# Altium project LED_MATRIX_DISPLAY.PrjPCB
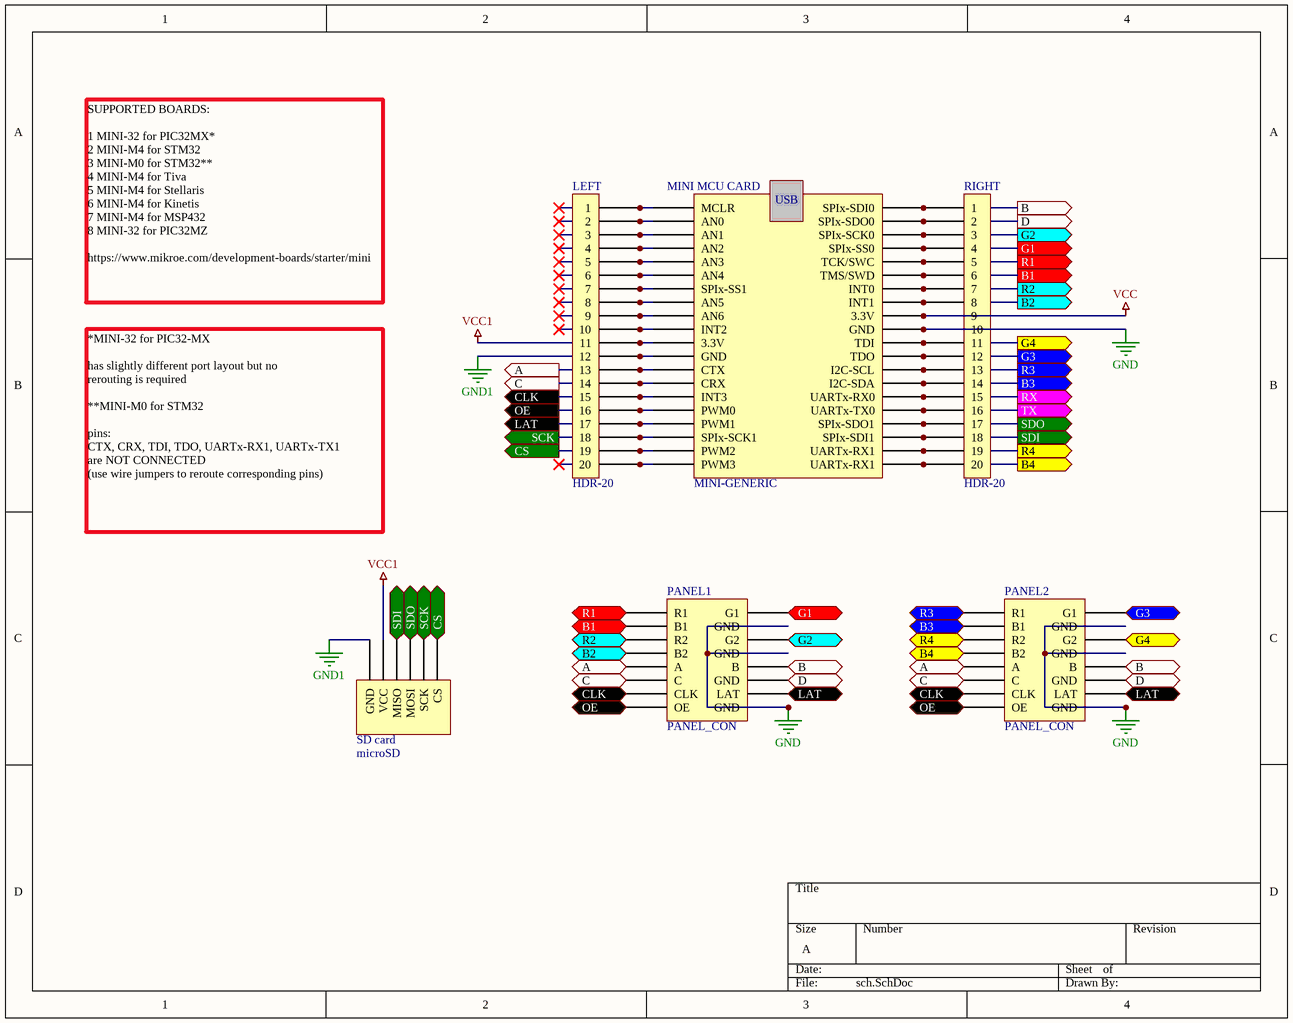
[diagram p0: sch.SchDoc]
1 sheet, 6 parts. Net scope: flat (ports and power ports of the same name join across sheets).
Board file: pcb.PcbDoc

## Sheet sch.SchDoc
size A

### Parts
LEFT  HDR-20  [HDR-20]
MINI_MCU_CARD  MINI-GENERIC  [MINI - GENERIC]
PANEL1  PANEL_CON  [HDR-8x2]
PANEL2  PANEL_CON  [HDR-8x2]
RIGHT  HDR-20  [HDR-20]
SD_card  microSD  [microSD]

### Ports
A (out), B1 (out), B2 (out), B3 (out), B4 (out), B (out), C (out), CLK (out), CS (out), D (out), G1 (out), G2 (out), G3 (out), G4 (out), LAT (out), OE (out), R1 (out), R2 (out), R3 (out), R4 (out), RX (out), SCK (out), SDI (out), SDO (out), TX (out)

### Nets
GND: MINI_MCU_CARD.31(GND) PANEL1.9(GND) PANEL1.13(GND) PANEL1.15(GND) PANEL2.9(GND) PANEL2.13(GND) PANEL2.15(GND) RIGHT.10
GND1: LEFT.12 MINI_MCU_CARD.12(GND) SD_card.1(GND)
VCC: MINI_MCU_CARD.32(3.3V) RIGHT.9
VCC1: LEFT.11 MINI_MCU_CARD.11(3.3V) SD_card.2(VCC)
NetLEFT_1: LEFT.1 MINI_MCU_CARD.1(MCLR)
NetLEFT_2: LEFT.2 MINI_MCU_CARD.2(AN0)
NetLEFT_3: LEFT.3 MINI_MCU_CARD.3(AN1)
NetLEFT_4: LEFT.4 MINI_MCU_CARD.4(AN2)
NetLEFT_5: LEFT.5 MINI_MCU_CARD.5(AN3)
NetLEFT_6: LEFT.6 MINI_MCU_CARD.6(AN4)
NetLEFT_7: LEFT.7 MINI_MCU_CARD.7(SPIx-SS1)
NetLEFT_8: LEFT.8 MINI_MCU_CARD.8(AN5)
NetLEFT_9: LEFT.9 MINI_MCU_CARD.9(AN6)
NetLEFT_10: LEFT.10 MINI_MCU_CARD.10(INT2)
NetLEFT_13: LEFT.13 MINI_MCU_CARD.13(CTX) PANEL1.5(A) PANEL2.5(A) ; port A
NetLEFT_14: LEFT.14 MINI_MCU_CARD.14(CRX) PANEL1.6(C) PANEL2.6(C) ; port C
NetLEFT_15: LEFT.15 MINI_MCU_CARD.15(INT3) PANEL1.7(CLK) PANEL2.7(CLK) ; port CLK
NetLEFT_16: LEFT.16 MINI_MCU_CARD.16(PWM0) PANEL1.8(OE) PANEL2.8(OE) ; port OE
NetLEFT_17: LEFT.17 MINI_MCU_CARD.17(PWM1) PANEL1.10(LAT) PANEL2.10(LAT) ; port LAT
NetLEFT_18: LEFT.18 MINI_MCU_CARD.18(SPIx-SCK1) SD_card.5(SCK) ; port SCK
NetLEFT_19: LEFT.19 MINI_MCU_CARD.19(PWM2) SD_card.6(CS) ; port CS
NetLEFT_20: LEFT.20 MINI_MCU_CARD.20(PWM3)
NetMINI_MCU_CARD_21: MINI_MCU_CARD.21(UARTx-RX1) PANEL2.4(B2) RIGHT.20 ; port B4
NetMINI_MCU_CARD_22: MINI_MCU_CARD.22(UARTx-RX1) PANEL2.3(R2) RIGHT.19 ; port R4
NetMINI_MCU_CARD_23: MINI_MCU_CARD.23(SPIx-SDI1) RIGHT.18 SD_card.3(MISO) ; port SDI
NetMINI_MCU_CARD_24: MINI_MCU_CARD.24(SPIx-SDO1) RIGHT.17 SD_card.4(MOSI) ; port SDO
NetMINI_MCU_CARD_25: MINI_MCU_CARD.25(UARTx-TX0) RIGHT.16 ; port TX
NetMINI_MCU_CARD_26: MINI_MCU_CARD.26(UARTx-RX0) RIGHT.15 ; port RX
NetMINI_MCU_CARD_27: MINI_MCU_CARD.27(I2C-SDA) PANEL2.2(B1) RIGHT.14 ; port B3
NetMINI_MCU_CARD_28: MINI_MCU_CARD.28(I2C-SCL) PANEL2.1(R1) RIGHT.13 ; port R3
NetMINI_MCU_CARD_29: MINI_MCU_CARD.29(TDO) PANEL2.16(G1) RIGHT.12 ; port G3
NetMINI_MCU_CARD_30: MINI_MCU_CARD.30(TDI) PANEL2.14(G2) RIGHT.11 ; port G4
NetMINI_MCU_CARD_33: MINI_MCU_CARD.33(INT1) PANEL1.4(B2) RIGHT.8 ; port B2
NetMINI_MCU_CARD_34: MINI_MCU_CARD.34(INT0) PANEL1.3(R2) RIGHT.7 ; port R2
NetMINI_MCU_CARD_35: MINI_MCU_CARD.35(TMS/SWD) PANEL1.2(B1) RIGHT.6 ; port B1
NetMINI_MCU_CARD_36: MINI_MCU_CARD.36(TCK/SWC) PANEL1.1(R1) RIGHT.5 ; port R1
NetMINI_MCU_CARD_37: MINI_MCU_CARD.37(SPIx-SS0) PANEL1.16(G1) RIGHT.4 ; port G1
NetMINI_MCU_CARD_38: MINI_MCU_CARD.38(SPIx-SCK0) PANEL1.14(G2) RIGHT.3 ; port G2
NetMINI_MCU_CARD_39: MINI_MCU_CARD.39(SPIx-SDO0) PANEL1.11(GND) PANEL2.11(GND) RIGHT.2 ; port D
NetMINI_MCU_CARD_40: MINI_MCU_CARD.40(SPIx-SDI0) PANEL1.12(B) PANEL2.12(B) RIGHT.1 ; port B

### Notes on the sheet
- SUPPORTED BOARDS:
  1 MINI-32 for PIC32MX*
  2 MINI-M4 for STM32
  3 MINI-M0 for STM32**
  4 MINI-M4 for Tiva
  5 MINI-M4 for Stellaris
  6 MINI-M4 for Kinetis
  7 MINI-M4 for MSP432
  8 MINI-32 for PIC32MZ
  https://www.mikroe.com/development-boards/starter/mini
- *MINI-32 for PIC32-MX
  has slightly different port layout but no
  rerouting is required
  **MINI-M0 for STM32
  pins:
  CTX, CRX, TDI, TDO, UARTx-RX1, UARTx-TX1
  are NOT CONNECTED
  (use wire jumpers to reroute corresponding pins)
